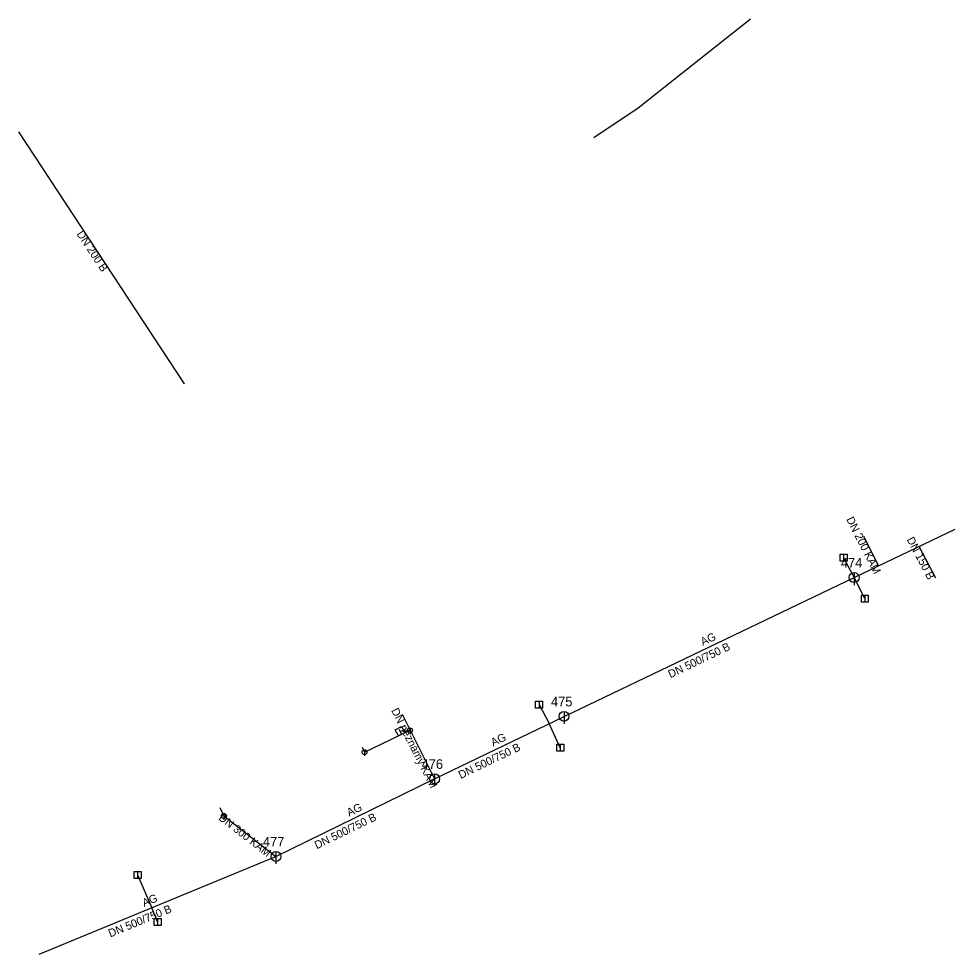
# Model space of a CAD drawing. Extents: x -492377 to -492189, y -1126311 to -1126123.
import ezdxf

# ---------------------------------------------------------------- set-up
doc = ezdxf.new("R2010")
doc.units = 0
for name, color, linetype in [('_pripojka_kanal_destova_priblizne_', 7, 'Continuous'), ('_pripojka_kanal_jednotna_priblizne_', 7, 'Continuous'), ('_stoka_jednotna_smvak_prevzato_z_dokumentace_', 7, 'Continuous'), ('Default', 7, 'Continuous'), ('MoLevel 119', 7, 'Continuous'), ('MoLevel 120', 7, 'Continuous'), ('MoLevel 124', 7, 'Continuous'), ('MoLevel 57', 7, 'Continuous'), ('MoLevel 63', 7, 'Continuous'), ('MoLevel 68', 7, 'Continuous'), ('MoLevel 69', 7, 'Continuous')]:
    doc.layers.add(name, color=color, linetype=linetype)

# ---------------------------------------------------------------- blocks, each defined once
blk = doc.blocks.new('_vpust_')
at = {"layer": 'Default'}
blk.add_line((0, 0.000025), (0, -0.000025), dxfattribs=at)
blk.add_lwpolyline([(-0.000035, 0.000035), (0.000035, 0.000035), (0.000035, -0.000035), (-0.000035, -0.000035), (-0.000035, 0.000035)], dxfattribs=at)
blk = doc.blocks.new('_sachta_kanal_prip_')
at = {"layer": 'Default'}
blk.add_line((0, 0.00005), (0, -0.000075), dxfattribs=at)
blk.add_circle((0, 0), 0.00005, dxfattribs=at)
blk = doc.blocks.new('_sachta_kanal_prevzato_z_dokumentace_')
at = {"layer": 'Default'}
blk.add_line((0, 0.00005), (0, -0.000075), dxfattribs=at)
blk.add_circle((0, 0), 0.00005, dxfattribs=at)

msp = doc.modelspace()

# ---------------------------------------------------------------- linework, layer by layer
at = {"layer": '_pripojka_kanal_destova_priblizne_'}
for p, q in [((-492211.66, -1126231.42), (-492209.55, -1126235.4)), ((-492207.4, -1126239.61), (-492209.55, -1126235.4)), ((-492272.74, -1126260.88), (-492270.71, -1126264.66)), ((-492268.48, -1126269.53), (-492270.71, -1126264.66)), ((-492300.62, -1126266.22), (-492298.61, -1126266.03)), ((-492353.24, -1126295.03), (-492350.42, -1126301.61)), ((-492349.23, -1126304.45), (-492350.42, -1126301.61))]:
    msp.add_line(p, q, dxfattribs=at)
at = {"layer": '_pripojka_kanal_jednotna_priblizne_'}
for p, q in [((-492207.66, -1126227.08), (-492204.64, -1126233.05)), ((-492193.16, -1126235.55), (-492196.51, -1126229.14)), ((-492300.19, -1126262.76), (-492298.61, -1126266.03)), ((-492307.74, -1126270.42), (-492298.61, -1126266.03)), ((-492298.61, -1126266.03), (-492293.67, -1126275.76)), ((-492308.19, -1126269.44), (-492307.74, -1126270.42)), ((-492336.78, -1126281.48), (-492335.94, -1126283.2)), ((-492335.94, -1126283.2), (-492325.49, -1126291.32))]:
    msp.add_line(p, q, dxfattribs=at)
for points in [[(-492261.77, -1126147.14), (-492252.88, -1126141.22), (-492230.33, -1126123.34)], [(-492343.85, -1126196.54), (-492343.85, -1126196.54), (-492343.85, -1126196.54), (-492343.85, -1126196.54), (-492377.08, -1126145.99)]]:
    msp.add_lwpolyline(points, dxfattribs=at)
at = {"layer": '_stoka_jednotna_smvak_prevzato_z_dokumentace_'}
for p, q in [((-492209.55, -1126235.4), (-492189.26, -1126225.67)), ((-492267.73, -1126263.23), (-492209.55, -1126235.4)), ((-492293.67, -1126275.76), (-492267.73, -1126263.23)), ((-492325.49, -1126291.32), (-492293.67, -1126275.76)), ((-492373.01, -1126310.94), (-492325.49, -1126291.32))]:
    msp.add_line(p, q, dxfattribs=at)

# ---------------------------------------------------------------- block references
at = {"layer": 'MoLevel 119', "xscale": 20000, "yscale": 20000}
for p in [(-492209.55, -1126235.4), (-492267.73, -1126263.23), (-492293.67, -1126275.76), (-492325.49, -1126291.32)]:
    msp.add_blockref('_sachta_kanal_prevzato_z_dokumentace_', p, dxfattribs=at)
at = {"layer": 'MoLevel 57', "xscale": 10000, "yscale": 10000}
for p in [(-492298.61, -1126266.03), (-492307.74, -1126270.42), (-492335.94, -1126283.2)]:
    msp.add_blockref('_sachta_kanal_prip_', p, dxfattribs=at)
at = {"layer": 'MoLevel 63', "xscale": 20000, "yscale": 20000}
for p in [(-492211.66, -1126231.42), (-492207.4, -1126239.61), (-492272.74, -1126260.88), (-492268.48, -1126269.53), (-492353.24, -1126295.03), (-492349.23, -1126304.45)]:
    msp.add_blockref('_vpust_', p, dxfattribs=at)
at = {"layer": 'MoLevel 63', "xscale": 20000, "yscale": 19999.999999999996, "rotation": 26.677837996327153}
msp.add_blockref('_vpust_', (-492300.62, -1126266.22), dxfattribs=at)

# ---------------------------------------------------------------- texts
at = {"layer": 'MoLevel 120'}
for s, p in [('474', (-492212.21, -1126233.4)), ('475', (-492270.34, -1126261.23)), ('476', (-492296.29, -1126273.76)), ('477', (-492328.1, -1126289.32))]:
    msp.add_text(s, height=1.926, dxfattribs=at).set_placement(p)
at = {"layer": 'MoLevel 124'}
for s, height, rotation, p in [('DN 200 B', 1.605, 303.3162, (-492365.53, -1126166.48)), ('DN 200 KAM', 1.605, 296.8292, (-492211.17, -1126223.69)), ('DN 150 B', 1.605, 297.6184, (-492199.05, -1126227.75)), ('DN neznámý KAM', 1.6049, 296.8955, (-492302.43, -1126262.05)), ('DN 300 KAM', 1.605, 322.1655, (-492337.15, -1126283.84))]:
    msp.add_text(s, height=height, rotation=rotation, dxfattribs=at).set_placement(p)
at = {"layer": 'MoLevel 68'}
for rotation, p in [(25.5591, (-492246.39, -1126255.6)), (25.7859, (-492288.43, -1126275.81)), (26.0601, (-492317.29, -1126289.89)), (22.4353, (-492358.71, -1126307.57))]:
    msp.add_text('DN 500/750 B', height=1.6049, rotation=rotation, dxfattribs=at).set_placement(p)
at = {"layer": 'MoLevel 69'}
for rotation, p in [(25.5591, (-492239.88, -1126249.11)), (25.7859, (-492281.94, -1126269.29)), (26.0601, (-492310.82, -1126283.34)), (22.4353, (-492351.94, -1126301.44))]:
    msp.add_text('AG', height=1.605, rotation=rotation, dxfattribs=at).set_placement(p)

doc.saveas('drawing.dxf')
